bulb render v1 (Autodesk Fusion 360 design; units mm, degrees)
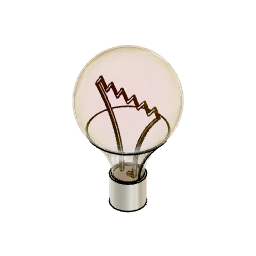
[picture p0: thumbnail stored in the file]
place_component sketch "Sketch6"
place_component sketch "Sketch6"
place_component sketch "Sketch6"
sketch "Sketch6" plane through (0, 0, 0) normal (0, 1, 0) x axis (1, 0, 0)
  line L1 (-25, 120) -> (25, 120)
  line L2 (-25, 165) -> (-25, 120)
  line L3 (25, 165) -> (-25, 165)
  line L4 (25, 120) -> (25, 165)
  line L5 (0, 120) -> (0, 0)
  curve K1 (22, 120) -> (56.5089, 49.3127)
  line L6 (22, 165) -> (22, 120)
  curve K2 (22, 128.4959) -> (22, 111.5041)
  line L7 (0, -75) -> (0, 0)
  line L8 (0, 165) -> (0, 0)
  line L9 (51.3755, -14.7247) -> (60, 0)
  line L10 (40, 0) -> (51.3755, -14.7247)
  line L11 (31.3755, -14.7247) -> (40, 0)
  line L12 (20, 0) -> (31.3755, -14.7247)
  line L13 (11.3755, -14.7247) -> (20, 0)
  line L14 (0, 0) -> (11.3755, -14.7247)
  line L15 (13.054, 120) -> (0, 120)
  line L16 (-51.3755, -14.7247) -> (-60, 0)
  line L17 (-40, 0) -> (-51.3755, -14.7247)
  line L18 (-31.3755, -14.7247) -> (-40, 0)
  line L19 (-20, 0) -> (-31.3755, -14.7247)
  line L20 (-11.3755, -14.7247) -> (-20, 0)
  line L21 (0, 0) -> (-11.3755, -14.7247)
  line L22 (10.0581, 117) -> (0, 117)
  line L23 (51.0328, -9.374) -> (56.2866, -0.4042)
  line L24 (39.6573, 5.3507) -> (51.0328, -9.374)
  line L25 (31.0328, -9.374) -> (39.6573, 5.3507)
  line L26 (19.6573, 5.3507) -> (31.0328, -9.374)
  line L27 (11.0328, -9.374) -> (19.6573, 5.3507)
  line L28 (0, 4.9071) -> (11.0328, -9.374)
  line L29 (0, 4.9071) -> (-11.0328, -9.374)
  line L30 (-11.0328, -9.374) -> (-19.6573, 5.3507)
  line L31 (-19.6573, 5.3507) -> (-31.0328, -9.374)
  line L32 (-31.0328, -9.374) -> (-39.6573, 5.3507)
  line L33 (-39.6573, 5.3507) -> (-51.0328, -9.374)
  line L34 (-51.0328, -9.374) -> (-56.2866, -0.4042)
  line L35 (55.9184, 0) -> (60, 0)
  line L36 (-60, 0) -> (-56.2866, -0.4042)
  circle C1 centre (0, 0) radius 75
  arc A1 centre (186.687, 118.7451) radius 173.6375 clockwise from (60, 0) to (13.054, 120)
  arc A2 centre (-186.687, 118.7451) radius 173.6375 clockwise from (-13.054, 120) to (-60, 0)
  arc A3 centre (186.687, 118.7451) radius 176.6375 clockwise from (56.2866, -0.4042) to (10.0581, 117)
  arc A4 centre (-186.687, 118.7451) radius 176.6375 clockwise from (-10.0541, 120.0217) to (-56.2866, -0.4042)
  point P1 (0, 0)
  point P2 (0, 0)
  point P7 (0, 0)
  point P8 (0, 120)
  point P9 (56.5089, 49.3127)
  point P10 (22, 120)
  point P11 (22, 165)
  point P14 (0, 0)
  point P15 (0, -75)
  point P16 (0, 0)
  point P17 (0, 165)
  point P19 (13.054, 120)
  point P26 (0, 0)
  point P18 (60, 0)
  point P29 (-60, 0)
  point P28 (-13.054, 120)
  point P21 (51.3755, -14.7247)
  point P30 (-51.3755, -14.7247)
  point P22 (40, 0)
  point P31 (-40, 0)
  point P23 (31.3755, -14.7247)
  point P32 (-31.3755, -14.7247)
  point P24 (20, 0)
  point P33 (-20, 0)
  point P25 (11.3755, -14.7247)
  point P34 (-11.3755, -14.7247)
  point P35 (0, 0)
  point P54 (55.9184, 0)
  point P5 (-25, 165)
  point P6 (25, 165)
  point P4 (-25, 120)
  point P3 (25, 120)
  coincident P1 P2
  horizontal L1
  vertical L2
  horizontal L3
  vertical L4
  coincident P1 P7
  midpoint L1 P8
  vertical L5
  coincident C1 P9
  coincident L1 P10
  tangent C1 K1
  coincident L3 P11
  perpendicular L3 L6
  midpoint P10 K2
  vertical K2
  coincident P2 P14
  coincident C1 P15
  parallel L5 L7
  coincident P2 P16
  midpoint L3 P17
  coincident L1 P19
  parallel L9 L11
  parallel L10 L12
  parallel L11 L13
  coincident P2 P26
  parallel L12 L14
  symmetric L8 P18 P29
  symmetric L8 P19 P28
  symmetric L8 A1 A2
  symmetric L8 P21 P30
  symmetric L8 P22 P31
  symmetric L8 P23 P32
  symmetric L8 P24 P33
  symmetric L8 P25 P34
  symmetric L8 P26 P35
  coincident A3 P54
  horizontal L35
  dimension "d11" distance P5 P6 = 50
  dimension "d12" diameter C1 = 150
  dimension "d13" distance P2 L1 = 120
  dimension "d14" distance P4 P5 = 45
  dimension "d15" distance P3 P10 = 3
  dimension "d19" = 3
extrude "Extrude1" new body sketch "Sketch6" profile of C1 L1 L8 A1 L15 A2 L22 A3 A4 L35 L36 distance 2
extrude "Extrude2" new body sketch "Sketch6" profile of L8 L9 L10 L11 L12 L13 L14 L16 L17 L18 L19 L20 L21 L25 A3 L24 L23 L26 L27 L28 L29 L30 L31 L32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 distance 1
revolve "Revolve1" sketch "Sketch6" AlongAngle 360 bodies "glass"
revolve "Revolve1" sketch "Sketch6" AlongAngle 360
shell "Shell1" sketch "Sketch6" innerThickness 2
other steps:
create_component "CreateComponent1"
create_component "CreateComponent1" sketch "Sketch6"
create_component "CreateComponent2" sketch "Sketch6"
create_component "CreateComponent3" sketch "Sketch6"
named bodies: "glass"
